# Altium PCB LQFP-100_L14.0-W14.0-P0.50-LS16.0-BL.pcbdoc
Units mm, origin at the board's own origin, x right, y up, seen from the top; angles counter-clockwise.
Board outline 29.4 x 29.73 mm, 2 copper layers (Top Layer, Bottom Layer); 1 components, 0 nets, 100 pads, 0 vias.
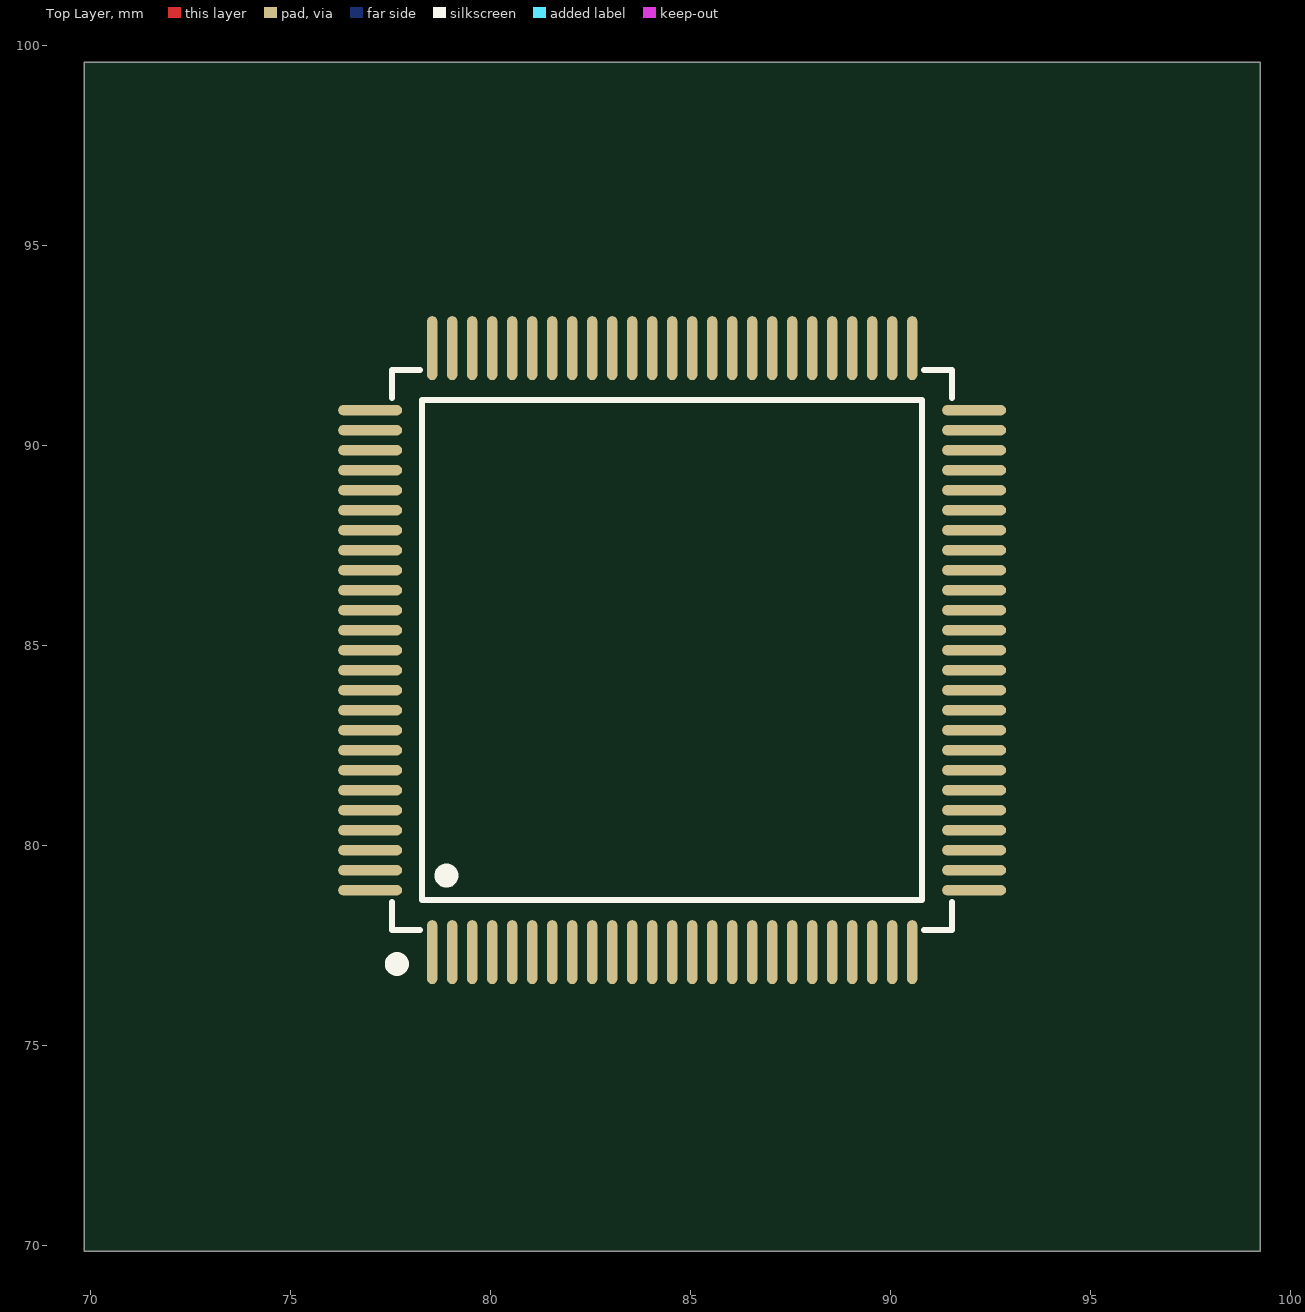
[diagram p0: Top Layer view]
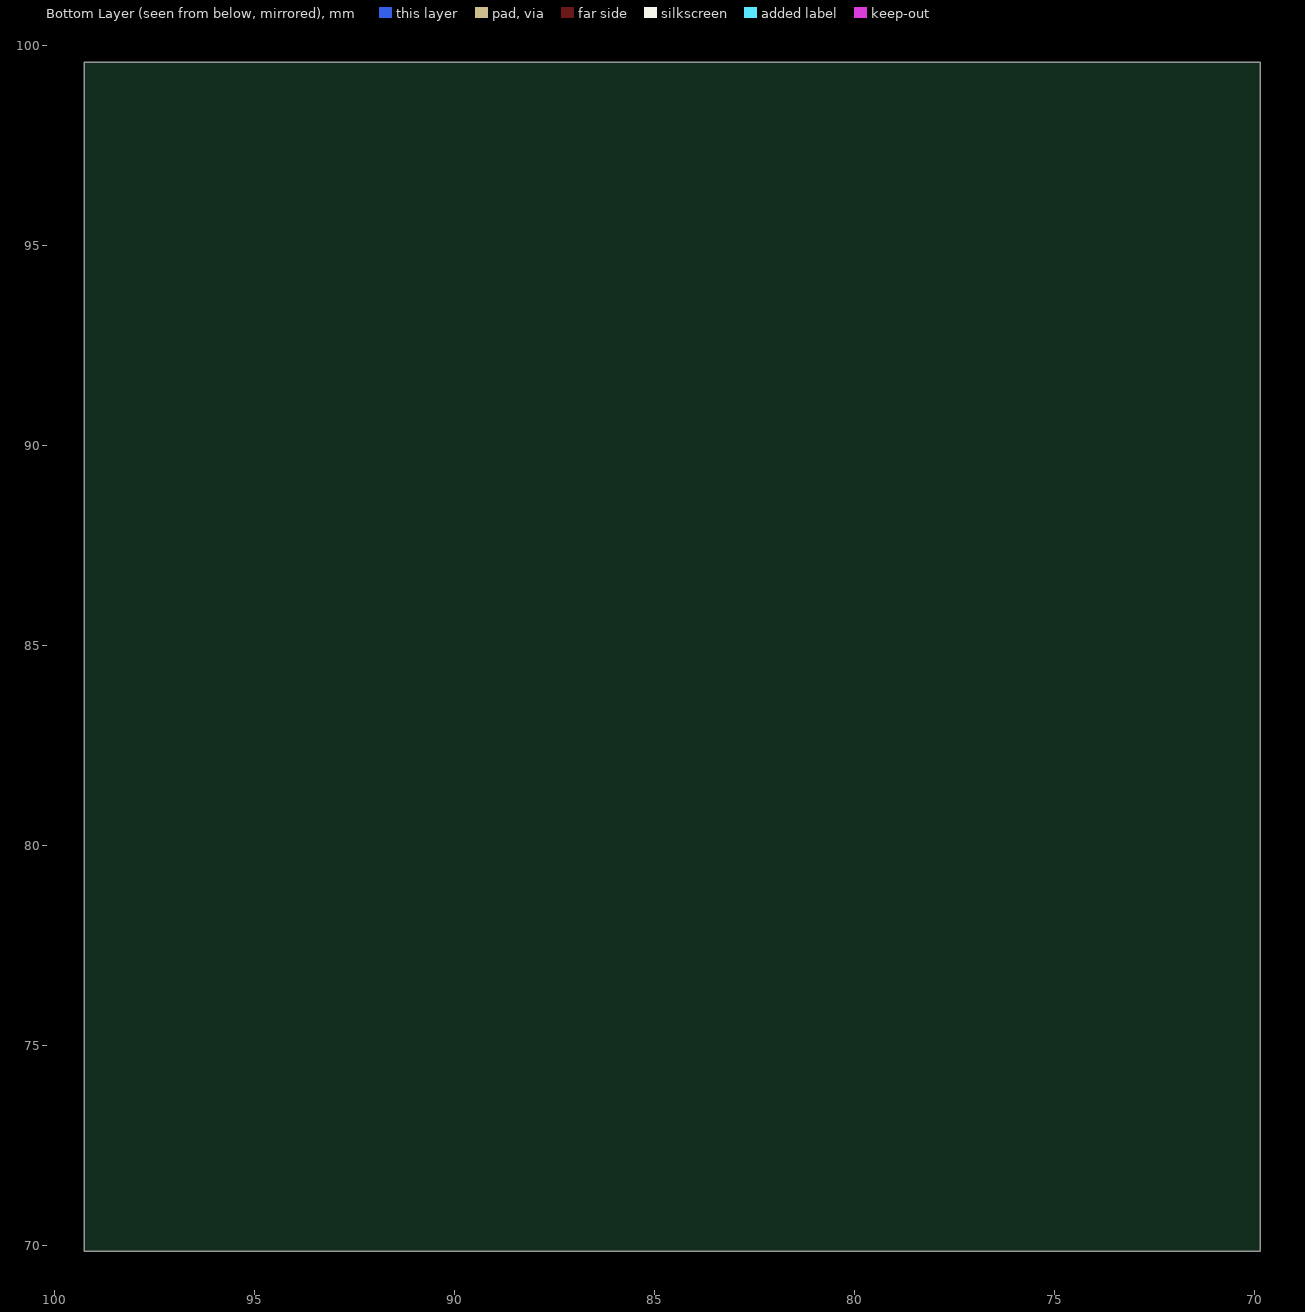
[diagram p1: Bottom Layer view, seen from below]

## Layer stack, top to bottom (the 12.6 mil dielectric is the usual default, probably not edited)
Top Layer: signal copper (thickness not stored)
Dielectric: dielectric 0.32, FR-4, Dk 4.8
Bottom Layer: signal copper (thickness not stored)

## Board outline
99.25,69.85 69.85,69.85 69.85,99.583 99.25,99.583

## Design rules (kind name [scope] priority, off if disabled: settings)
BoardOutlineClearance safeClearance [All] p0: genericclearance=0.254 ignorepadtopadclearanceinfootprint=FALSE except(0: Arc-SplitContinuation Track-SplitContinuation SMDPad-SplitContinuation THPad-SplitContinuation Via-SplitContinuation Fill-SplitContinuation Poly-SplitContinuation Region-SplitContinuation Text-SplitContinuation; 0.152: Track-CutoutEdge SMDPad-CutoutEdge THPad-CutoutEdge Via-CutoutEdge Fill-CutoutEdge Region-CutoutEdge; 0.3: Track-OutlineEdge SMDPad-OutlineEdge THPad-OutlineEdge Via-OutlineEdge Fill-OutlineEdge Region-OutlineEdge Poly-OutlineEdge Text-OutlineEdge)
Clearance safeClearance [All] p1: gap=0.178 ignorepadtopadclearanceinfootprint=FALSE except(0.152: Track-Track Track-SMDPad SMDPad-SMDPad Track-THPad SMDPad-THPad THPad-THPad Track-Via SMDPad-Via THPad-Via Via-Via Track-Fill SMDPad-Fill THPad-Fill Via-Fill Fill-Fill Track-Region SMDPad-Region THPad-Region Via-Region Fill-Region Region-Region Track-Poly SMDPad-Poly THPad-Poly Via-Poly Fill-Poly Region-Poly Poly-Poly Track-Text SMDPad-Text THPad-Text Via-Text Fill-Text Region-Text Poly-Text Text-Text; 0.175: Track-Hole SMDPad-Hole THPad-Hole Via-Hole Fill-Hole Region-Hole Poly-Hole Text-Hole Sheet-Hole; 0.3: Track-Sheet SMDPad-Sheet THPad-Sheet Via-Sheet Fill-Sheet Region-Sheet Poly-Sheet Text-Sheet)
DiffPairsRouting differentialPair [All] p1: maxuncoupledlength=10 minlimit=6 maxlimit=6 mostfreqgap=6 toplayer_minwidth=5 toplayer_prefwidth=10 toplayer_maxwidth=100 bottomlayer_minwidth=5 bottomlayer_prefwidth=10 bottomlayer_maxwidth=100
PasteMaskExpansion pasteMaskExpansion [All] p1: expansion=0
PlaneConnect innerPlane [All] p1: planeconnectstyle=Relief reliefexpansion=0.508 reliefentries=4 reliefconductorwidth=0.254 reliefairgap=0.254
PolygonConnect copperRegion [All] p1: connectstyle=Relief reliefentries=4 reliefconductorwidth=10 polygonreliefangle="90 Angle" airgapwidth=10
RoutingVias viaSize [All] p1: viastyle="Through Hole" holewidth=12.0078 minholewidth=11.811 maxholewidth=236.2204 width=24.0158 minwidth=19.685 maxwidth=393.7008
SolderMaskExpansion solderMaskExpansion [All] p1: useseparateexpansions=TRUE expansion=2 expansionbottom=2
Width trackWidth [All] p1: maxlimit=100 minlimit=5 preferedwidth=10

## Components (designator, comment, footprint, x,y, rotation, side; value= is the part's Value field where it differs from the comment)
? "LQFP-100_L14.0-W14.0-P0.50-LS16.0-BL" LQFP-100_L14.0-W14.0-P0.50-LS16.0-BL 84.55,84.883 r0 top

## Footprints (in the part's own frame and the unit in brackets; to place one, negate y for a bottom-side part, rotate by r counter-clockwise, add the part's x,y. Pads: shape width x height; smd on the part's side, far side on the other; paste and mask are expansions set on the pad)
LQFP-100_L14.0-W14.0-P0.50-LS16.0-BL [mm]
  oval 0.26x1.6 smd: 1(-6,-7.55) 2(-5.5,-7.55) 3(-5,-7.55) 4(-4.5,-7.55) 5(-4,-7.55) 6(-3.5,-7.55) 7(-3,-7.55) 8(-2.5,-7.55) 9(-2,-7.55) 10(-1.5,-7.55) 11(-1,-7.55) 12(-0.5,-7.55) 13(0,-7.55) 14(0.5,-7.55) 15(1,-7.55) 16(1.5,-7.55) 17(2,-7.55) 18(2.5,-7.55) 19(3,-7.55) 20(3.5,-7.55) 21(4,-7.55) 22(4.5,-7.55) 23(5,-7.55) 24(5.5,-7.55) 25(6,-7.55) 51(6,7.55) 52(5.5,7.55) 53(5,7.55) 54(4.5,7.55) 55(4,7.55) 56(3.5,7.55) 57(3,7.55) 58(2.5,7.55) 59(2,7.55) 60(1.5,7.55) 61(1,7.55) 62(0.5,7.55) 63(0,7.55) 64(-0.5,7.55) 65(-1,7.55) 66(-1.5,7.55) 67(-2,7.55) 68(-2.5,7.55) 69(-3,7.55) 70(-3.5,7.55) 71(-4,7.55) 72(-4.5,7.55) 73(-5,7.55) 74(-5.5,7.55) 75(-6,7.55)
  oval 1.6x0.26 smd: 26(7.55,-6) 27(7.55,-5.5) 28(7.55,-5) 29(7.55,-4.5) 30(7.55,-4) 31(7.55,-3.5) 32(7.55,-3) 33(7.55,-2.5) 34(7.55,-2) 35(7.55,-1.5) 36(7.55,-1) 37(7.55,-0.5) 38(7.55,0) 39(7.55,0.5) 40(7.55,1) 41(7.55,1.5) 42(7.55,2) 43(7.55,2.5) 44(7.55,3) 45(7.55,3.5) 46(7.55,4) 47(7.55,4.5) 48(7.55,5) 49(7.55,5.5) 50(7.55,6) 76(-7.55,6) 77(-7.55,5.5) 78(-7.55,5) 79(-7.55,4.5) 80(-7.55,4) 81(-7.55,3.5) 82(-7.55,3) 83(-7.55,2.5) 84(-7.55,2) 85(-7.55,1.5) 86(-7.55,1) 87(-7.55,0.5) 88(-7.55,0) 89(-7.55,-0.5) 90(-7.55,-1) 91(-7.55,-1.5) 92(-7.55,-2) 93(-7.55,-2.5) 94(-7.55,-3) 95(-7.55,-3.5) 96(-7.55,-4) 97(-7.55,-4.5) 98(-7.55,-5) 99(-7.55,-5.5) 100(-7.55,-6)
  silkscreen extent -7.03,-8 7,7

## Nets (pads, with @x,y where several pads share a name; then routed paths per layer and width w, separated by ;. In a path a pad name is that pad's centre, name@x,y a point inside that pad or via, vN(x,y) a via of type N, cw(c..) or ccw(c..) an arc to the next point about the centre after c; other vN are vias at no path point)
pads on no net: ?.1 ?.2 ?.3 ?.4 ?.5 ?.6 ?.7 ?.8 ?.9 ?.10 ?.11 ?.12 ?.13 ?.14 ?.15 ?.16 ?.17 ?.18 ?.19 ?.20 ?.21 ?.22 ?.23 ?.24 ?.25 ?.26 ?.27 ?.28 ?.29 ?.30 ?.31 ?.32 ?.33 ?.34 ?.35 ?.36 ?.37 ?.38 ?.39 ?.40 ?.41 ?.42 ?.43 ?.44 ?.45 ?.46 ?.47 ?.48 ?.49 ?.50 ?.51 ?.52 ?.53 ?.54 ?.55 ?.56 ?.57 ?.58 ?.59 ?.60 ?.61 ?.62 ?.63 ?.64 ?.65 ?.66 ?.67 ?.68 ?.69 ?.70 ?.71 ?.72 ?.73 ?.74 ?.75 ?.76 ?.77 ?.78 ?.79 ?.80 ?.81 ?.82 ?.83 ?.84 ?.85 ?.86 ?.87 ?.88 ?.89 ?.90 ?.91 ?.92 ?.93 ?.94 ?.95 ?.96 ?.97 ?.98 ?.99 ?.100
